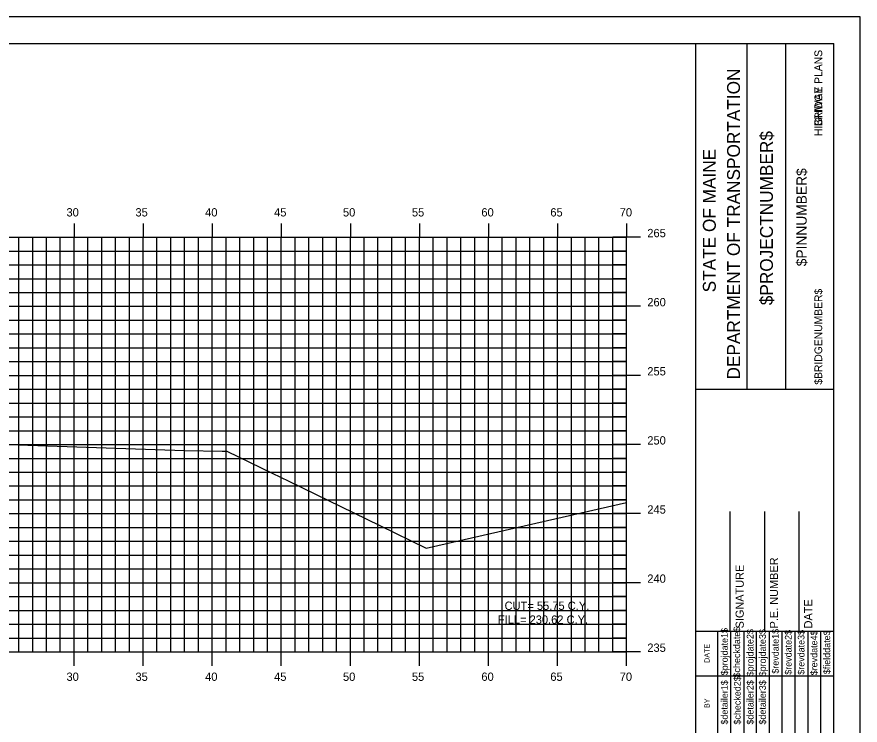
# Model space of a CAD drawing. Extents: x 1170543 to 1177585, y 609599 to 610623.
# Drawn here: x 1175161.2 to 1175222.2, y 609657.6 to 609708.8 of the extents above; entities that cross this region are included whole.
import ezdxf

# ---------------------------------------------------------------- set-up
doc = ezdxf.new("R2010")
doc.units = 0
for name, color, linetype in [('BORDER', 7, 'Continuous'), ('BRIDGE_TITLE', 7, 'Continuous'), ('D_Roadway_Centerline_Text', 7, 'Continuous'), ('H_V ANNOTATION', 7, 'Continuous'), ('HIGHWAY_TITLE', 7, 'Continuous'), ('MAJOR', 7, 'Continuous'), ('MINOR', 7, 'Continuous'), ('PLOT BOUNDARY', 7, 'Continuous'), ('S_Roadway_Centerline', 7, 'Continuous')]:
    doc.layers.add(name, color=color, linetype=linetype)

msp = doc.modelspace()

# ---------------------------------------------------------------- linework, layer by layer
at = {"layer": 'BORDER'}
for p, q in [((1175220.313, 609706.872), (1175060.313, 609706.872)), ((1175210.313, 609601.875), (1175210.313, 609706.875)), ((1175214.042, 609681.869), (1175214.042, 609706.869)), ((1175216.837, 609681.869), (1175216.837, 609706.869)), ((1175220.313, 609601.875), (1175220.313, 609706.875)), ((1175210.314, 609681.866), (1175220.313, 609681.866)), ((1175212.813, 609664.375), (1175212.813, 609673.023)), ((1175215.313, 609664.375), (1175215.313, 609673.023)), ((1175217.813, 609664.375), (1175217.813, 609673.023)), ((1175210.313, 609664.375), (1175220.313, 609664.375))]:
    msp.add_line(p, q, dxfattribs=at)
for points in [[(1175211.928, 609661.125), (1175211.928, 609664.375)], [(1175212.861, 609646.878), (1175212.861, 609664.375)], [(1175213.792, 609664.375), (1175213.792, 609646.878)], [(1175214.724, 609646.878), (1175214.724, 609664.375)], [(1175215.656, 609646.878), (1175215.656, 609664.375)], [(1175216.587, 609646.878), (1175216.587, 609664.375)], [(1175217.519, 609646.878), (1175217.519, 609664.375)], [(1175218.451, 609646.878), (1175218.451, 609664.375)], [(1175219.382, 609646.878), (1175219.382, 609664.375)], [(1175211.929, 609646.878), (1175211.929, 609663.669)], [(1175210.313, 609661.125), (1175220.313, 609661.125)]]:
    msp.add_lwpolyline(points, dxfattribs=at)
at = {"layer": 'MAJOR'}
for p, q in [((1175165.313, 609693.874), (1175165.313, 609692.872)), ((1175170.313, 609693.874), (1175170.313, 609692.872)), ((1175175.313, 609693.874), (1175175.313, 609692.872)), ((1175180.313, 609693.874), (1175180.313, 609692.872)), ((1175185.313, 609693.874), (1175185.313, 609692.872)), ((1175190.313, 609693.874), (1175190.313, 609692.872)), ((1175195.313, 609693.874), (1175195.313, 609692.872)), ((1175200.313, 609693.874), (1175200.313, 609692.872)), ((1175205.313, 609693.874), (1175205.313, 609692.872)), ((1175065.313, 609692.872), (1175205.313, 609692.872)), ((1175065.313, 609692.872), (1175205.313, 609692.872)), ((1175165.313, 609662.872), (1175165.313, 609692.872)), ((1175170.313, 609662.872), (1175170.313, 609692.872)), ((1175175.313, 609662.872), (1175175.313, 609692.872)), ((1175180.313, 609662.872), (1175180.313, 609692.872)), ((1175185.313, 609662.872), (1175185.313, 609692.872)), ((1175190.313, 609662.872), (1175190.313, 609692.872)), ((1175195.313, 609662.872), (1175195.313, 609692.872)), ((1175200.313, 609662.872), (1175200.313, 609692.872)), ((1175206.315, 609692.872), (1175204.311, 609692.872)), ((1175205.313, 609662.872), (1175205.313, 609692.872)), ((1175205.313, 609662.872), (1175205.313, 609692.872)), ((1175065.313, 609687.872), (1175205.313, 609687.872)), ((1175206.315, 609687.872), (1175204.311, 609687.872)), ((1175065.313, 609682.872), (1175205.313, 609682.872)), ((1175206.315, 609682.872), (1175204.311, 609682.872)), ((1175065.313, 609677.872), (1175205.313, 609677.872)), ((1175206.315, 609677.872), (1175204.311, 609677.872)), ((1175065.313, 609672.872), (1175205.313, 609672.872)), ((1175206.315, 609672.872), (1175204.311, 609672.872)), ((1175065.313, 609667.872), (1175205.313, 609667.872)), ((1175206.315, 609667.872), (1175204.311, 609667.872)), ((1175065.313, 609662.872), (1175205.313, 609662.872)), ((1175065.313, 609662.872), (1175205.313, 609662.872)), ((1175165.313, 609661.87), (1175165.313, 609662.872)), ((1175170.313, 609661.87), (1175170.313, 609662.872)), ((1175175.313, 609661.87), (1175175.313, 609662.872)), ((1175180.313, 609661.87), (1175180.313, 609662.872)), ((1175185.313, 609661.87), (1175185.313, 609662.872)), ((1175190.313, 609661.87), (1175190.313, 609662.872)), ((1175195.313, 609661.87), (1175195.313, 609662.872)), ((1175200.313, 609661.87), (1175200.313, 609662.872)), ((1175206.315, 609662.872), (1175204.311, 609662.872)), ((1175205.313, 609661.87), (1175205.313, 609662.872))]:
    msp.add_line(p, q, dxfattribs=at)
at = {"layer": 'MINOR'}
for p, q in [((1175161.313, 609662.872), (1175161.313, 609692.872)), ((1175162.313, 609662.872), (1175162.313, 609692.872)), ((1175163.313, 609662.872), (1175163.313, 609692.872)), ((1175164.313, 609662.872), (1175164.313, 609692.872)), ((1175166.313, 609662.872), (1175166.313, 609692.872)), ((1175167.313, 609662.872), (1175167.313, 609692.872)), ((1175168.313, 609662.872), (1175168.313, 609692.872)), ((1175169.313, 609662.872), (1175169.313, 609692.872)), ((1175171.313, 609662.872), (1175171.313, 609692.872)), ((1175172.313, 609662.872), (1175172.313, 609692.872)), ((1175173.313, 609662.872), (1175173.313, 609692.872)), ((1175174.313, 609662.872), (1175174.313, 609692.872)), ((1175176.313, 609662.872), (1175176.313, 609692.872)), ((1175177.313, 609662.872), (1175177.313, 609692.872)), ((1175178.313, 609662.872), (1175178.313, 609692.872)), ((1175179.313, 609662.872), (1175179.313, 609692.872)), ((1175181.313, 609662.872), (1175181.313, 609692.872)), ((1175182.313, 609662.872), (1175182.313, 609692.872)), ((1175183.313, 609662.872), (1175183.313, 609692.872)), ((1175184.313, 609662.872), (1175184.313, 609692.872)), ((1175186.313, 609662.872), (1175186.313, 609692.872)), ((1175187.313, 609662.872), (1175187.313, 609692.872)), ((1175188.313, 609662.872), (1175188.313, 609692.872)), ((1175189.313, 609662.872), (1175189.313, 609692.872)), ((1175191.313, 609662.872), (1175191.313, 609692.872)), ((1175192.313, 609662.872), (1175192.313, 609692.872)), ((1175193.313, 609662.872), (1175193.313, 609692.872)), ((1175194.313, 609662.872), (1175194.313, 609692.872)), ((1175196.313, 609662.872), (1175196.313, 609692.872)), ((1175197.313, 609662.872), (1175197.313, 609692.872)), ((1175198.313, 609662.872), (1175198.313, 609692.872)), ((1175199.313, 609662.872), (1175199.313, 609692.872)), ((1175201.313, 609662.872), (1175201.313, 609692.872)), ((1175202.313, 609662.872), (1175202.313, 609692.872)), ((1175203.313, 609662.872), (1175203.313, 609692.872)), ((1175204.313, 609662.872), (1175204.313, 609692.872)), ((1175065.313, 609691.872), (1175205.313, 609691.872)), ((1175205.313, 609691.872), (1175204.311, 609691.872)), ((1175065.313, 609690.872), (1175205.313, 609690.872)), ((1175205.313, 609690.872), (1175204.311, 609690.872)), ((1175065.313, 609689.872), (1175205.313, 609689.872)), ((1175205.313, 609689.872), (1175204.311, 609689.872)), ((1175065.313, 609688.872), (1175205.313, 609688.872)), ((1175205.313, 609688.872), (1175204.311, 609688.872)), ((1175065.313, 609686.872), (1175205.313, 609686.872)), ((1175205.313, 609686.872), (1175204.311, 609686.872)), ((1175065.313, 609685.872), (1175205.313, 609685.872)), ((1175205.313, 609685.872), (1175204.311, 609685.872)), ((1175065.313, 609684.872), (1175205.313, 609684.872)), ((1175205.313, 609684.872), (1175204.311, 609684.872)), ((1175065.313, 609683.872), (1175205.313, 609683.872)), ((1175205.313, 609683.872), (1175204.311, 609683.872)), ((1175065.313, 609681.872), (1175205.313, 609681.872)), ((1175205.313, 609681.872), (1175204.311, 609681.872)), ((1175065.313, 609680.872), (1175205.313, 609680.872)), ((1175205.313, 609680.872), (1175204.311, 609680.872)), ((1175065.313, 609679.872), (1175205.313, 609679.872)), ((1175205.313, 609679.872), (1175204.311, 609679.872)), ((1175065.313, 609678.872), (1175205.313, 609678.872)), ((1175205.313, 609678.872), (1175204.311, 609678.872)), ((1175065.313, 609676.872), (1175205.313, 609676.872)), ((1175205.313, 609676.872), (1175204.311, 609676.872)), ((1175065.313, 609675.872), (1175205.313, 609675.872)), ((1175205.313, 609675.872), (1175204.311, 609675.872)), ((1175065.313, 609674.872), (1175205.313, 609674.872)), ((1175205.313, 609674.872), (1175204.311, 609674.872)), ((1175065.313, 609673.872), (1175205.313, 609673.872)), ((1175205.313, 609673.872), (1175204.311, 609673.872)), ((1175065.313, 609671.872), (1175205.313, 609671.872)), ((1175205.313, 609671.872), (1175204.311, 609671.872)), ((1175065.313, 609670.872), (1175205.313, 609670.872)), ((1175205.313, 609670.872), (1175204.311, 609670.872)), ((1175065.313, 609669.872), (1175205.313, 609669.872)), ((1175205.313, 609669.872), (1175204.311, 609669.872)), ((1175065.313, 609668.872), (1175205.313, 609668.872)), ((1175205.313, 609668.872), (1175204.311, 609668.872)), ((1175065.313, 609666.872), (1175205.313, 609666.872)), ((1175205.313, 609666.872), (1175204.311, 609666.872)), ((1175065.313, 609665.872), (1175205.313, 609665.872)), ((1175205.313, 609665.872), (1175204.311, 609665.872)), ((1175065.313, 609664.872), (1175205.313, 609664.872)), ((1175205.313, 609664.872), (1175204.311, 609664.872)), ((1175065.313, 609663.872), (1175205.313, 609663.872)), ((1175205.313, 609663.872), (1175204.311, 609663.872))]:
    msp.add_line(p, q, dxfattribs=at)
at = {"layer": 'PLOT BOUNDARY'}
msp.add_lwpolyline([(1175052.22, 609598.813), (1175222.22, 609598.813), (1175222.22, 609708.813), (1175052.22, 609708.813)], close=True, dxfattribs=at)
at = {"layer": 'S_Roadway_Centerline'}
msp.add_lwpolyline([(1175157.698, 609677.964), (1175173.31, 609677.436), (1175176.042, 609677.397), (1175176.362, 609677.393), (1175179.649, 609675.794), (1175180.85, 609675.212), (1175187.444, 609672.006), (1175190.809, 609670.37), (1175205.313, 609673.68)], dxfattribs=at)

# ---------------------------------------------------------------- texts
at = {"layer": 'BORDER'}
for s, height, p in [('DEPARTMENT OF TRANSPORTATION', 0.93176, (1175213.52, 609682.578)), ('$PROJECTNUMBER$', 0.93176, (1175215.905, 609687.951)), ('STATE OF MAINE', 0.93176, (1175211.769, 609688.884)), ('$PINNUMBER$', 0.74527, (1175218.35, 609690.769)), ('P.E. NUMBER', 0.59055, (1175216.274, 609664.567)), ('SIGNATURE', 0.5906, (1175213.794, 609664.567)), ('DATE', 0.5906, (1175218.754, 609664.567)), ('$projdate1$', 0.48455, (1175212.636, 609661.176)), ('$checkdate$', 0.48455, (1175213.531, 609661.018)), ('$projdate2$', 0.48455, (1175214.5, 609661.097)), ('$projdate3$', 0.48455, (1175215.394, 609661.097)), ('$revdate1$', 0.4845, (1175216.326, 609661.294)), ('$revdate2$', 0.4845, (1175217.257, 609661.215)), ('$revdate3$', 0.4845, (1175218.189, 609661.215)), ('$revdate4$', 0.4845, (1175219.121, 609661.176)), ('$fielddate$', 0.48455, (1175220.052, 609661.254)), ('DATE', 0.3714, (1175211.318, 609662.081)), ('$checked2$', 0.4845, (1175213.568, 609657.61)), ('$detailer1$', 0.48455, (1175212.636, 609657.61)), ('$detailer2$', 0.48455, (1175214.5, 609657.61)), ('$detailer3$', 0.48455, (1175215.394, 609657.61)), ('BY', 0.3714, (1175211.318, 609658.81))]:
    msp.add_text(s, height=height, rotation=90, dxfattribs=at).set_placement(p)
at = {"layer": 'BRIDGE_TITLE'}
for s, p in [('BRIDGE PLANS', (1175219.472, 609700.897)), ('$BRIDGENUMBER$', (1175219.472, 609682.203))]:
    msp.add_text(s, height=0.55901, rotation=90, dxfattribs=at).set_placement(p)
at = {"layer": 'D_Roadway_Centerline_Text'}
for s, p in [('CUT= 55.75 C.Y.', (1175196.479, 609665.908)), ('FILL= 230.62 C.Y.', (1175195.992, 609664.906))]:
    msp.add_text(s, height=0.6, dxfattribs=at).set_placement(p)
at = {"layer": 'H_V ANNOTATION'}
for s, p in [('30', (1175164.762, 609694.372)), ('35', (1175169.754, 609694.372)), ('40', (1175174.799, 609694.372)), ('45', (1175179.791, 609694.372)), ('50', (1175184.778, 609694.372)), ('55', (1175189.77, 609694.372)), ('60', (1175194.799, 609694.372)), ('65', (1175199.791, 609694.372)), ('70', (1175204.815, 609694.372)), ('265', (1175206.813, 609692.872)), ('260', (1175206.813, 609687.872)), ('255', (1175206.813, 609682.872)), ('250', (1175206.813, 609677.872)), ('245', (1175206.813, 609672.872)), ('240', (1175206.813, 609667.872)), ('235', (1175206.813, 609662.872)), ('30', (1175164.762, 609660.772)), ('35', (1175169.754, 609660.772)), ('40', (1175174.799, 609660.772)), ('45', (1175179.791, 609660.772)), ('50', (1175184.778, 609660.772)), ('55', (1175189.77, 609660.772)), ('60', (1175194.799, 609660.772)), ('65', (1175199.791, 609660.772)), ('70', (1175204.815, 609660.772))]:
    msp.add_text(s, height=0.6, dxfattribs=at).set_placement(p)
at = {"layer": 'HIGHWAY_TITLE'}
msp.add_text('HIGHWAY PLANS', height=0.55901, rotation=90, dxfattribs=at).set_placement((1175219.472, 609700.188))

doc.saveas('drawing.dxf')
